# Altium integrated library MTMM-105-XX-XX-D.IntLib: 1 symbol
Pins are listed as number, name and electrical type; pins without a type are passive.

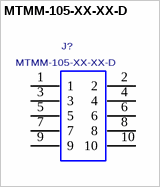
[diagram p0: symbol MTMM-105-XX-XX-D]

## MTMM-105-XX-XX-D
designator J?
2MM TERMINAL STRIP ASSEMBLY.; MANUFACTURER: SAMTEC
footprint MTMM-105-XX-XX-D
pins: 1, 2, 3, 4, 5, 6, 7, 8, 9, 10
